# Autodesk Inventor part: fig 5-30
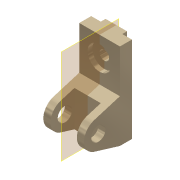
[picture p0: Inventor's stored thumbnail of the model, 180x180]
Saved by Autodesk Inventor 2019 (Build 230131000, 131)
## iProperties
Shininess: 65.0
Angle Display Precision: 2
Document Length Units: 11269
Document Angle Units: 11279
Document Time Units: 11290
Document Mass Units: 11283
Document Length Units Precision: 3
Document Angle Units Precision: 2
Created: 2001-11
Part Number: fig 5-30
Document SubType Name: Modeling
Designer: Renu Muthoo
Density: 1 g/cm^3
Material: Generic
Appearance: Metal-Titanium (Polished)
Density: 0.0
Volumn: 0.0
Area: 0.0
PropertySet Name: Model Information
Control State: 0
Master: False
Checked Out: False
Author: Renu Muthoo
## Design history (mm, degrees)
node "Sketch1"
sketch "Sketch2"
  geometry: L1 (33.257, 104.664)-(33.257, -75.336); L2 (33.257, -75.336)-(8.257, -75.336); L3 (8.257, -75.336)-(-45.451, -59.045); L4 (-45.451, -1.628)-(8.257, 14.664); L5 (8.257, 14.664)-(8.257, 104.664); L6 (8.257, 104.664)-(33.257, 104.664); C1 r 15 at (-36.743, -30.336); A1 r 30 centre (-36.743, -30.336) between (-45.451, -1.628) and (-45.451, -59.045)
  constraints: 12 end point, 2 centre point, 2 equal length, 2 parallel, 2 point on circle, 2 tangent, 1 coincident, 1 perpendicular, 1 vertical
  dimensions: "d0" = 180 distance of L1.start L1.end; "d1" = 30 radius of A1; "d2" = 25 distance of L5.end L1.start; "d3" = 45 distance from line of L2 A1.centre; "d4" = 70 distance from line of L1 A1.centre; "d5" = 30 diameter of C1
extrude "Extrusion1" new body sketch "Sketch2" distance "d6" = 85; taper "d7" = 0 deg
workplane "Work Plane1"
sketch "Sketch3"
  geometry: L1 (15, 62.364)-(70, 62.364); L2 (70, 62.364)-(70, -52.386); L3 (70, -52.386)-(15, -52.386); L4 (15, -52.386)-(15, 62.364); L5 (0, -45)-(0, -28.708) reference
  constraints: 8 end point, 2 parallel, 1 horizontal, 1 perpendicular
  dimensions: "d8" = 55 distance of L1.start L1.end; "d9" = 15 distance between parallel lines of L5 L4
extrude "Extrusion2" cut sketch "Sketch3" distance "d10" = 50; taper "d11" = 0 deg
sketch "Sketch4"
  geometry: L1 (0, 25)-(85, 25) reference; L2 (0, 0)-(0, 25) reference; L3 (20, 25)-(65, 25); L4 (65, 25)-(65, 35); L5 (65, 35)-(20, 35); L6 (20, 35)-(20, 25)
  constraints: 8 end point, 2 parallel, 1 horizontal, 1 perpendicular, 1 point on line
  dimensions: "d12" = 45 distance of L4.end L5.end; "d13" = 10 distance of L3.end L4.end; "d14" = 20 distance between parallel lines of L2 L6
extrude "Extrusion3" join sketch "Sketch4" stored distance "d15" = 50; taper "d16" = 0 deg
sketch "Sketch5"
  geometry: L1 (85, 0)-(85, 90) reference; L2 (0, 90)-(85, 90) reference; 1 further point
  dimensions: "d17" = 42 distance from line of L2 point (42.5, 48); "d18" = 42.5 distance from line of L1 point (42.5, 48)
hole "Hole1" sketch "Sketch5" at (42.5, 48) diameter "d19" = 20; stored, may be unused: countersink angle "d23" = 82 deg, drill point angle "d25" = 118 deg; dims "d20" = 6, "d21" = 50, "d22" = 10, "d24" = 8
workplane "Work Plane5"
body "Solid1"
